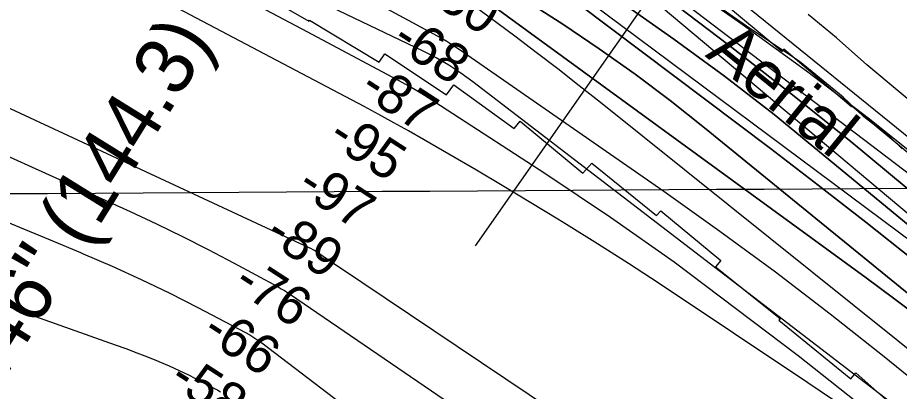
# Model space of a CAD drawing. Extents: x 3477039 to 3515015, y 546746 to 572297.
# Drawn here: x 3498864 to 3500384, y 563990 to 564634 of the extents above; entities that cross this region are included whole.
import ezdxf

# ---------------------------------------------------------------- set-up
doc = ezdxf.new("R2010")
doc.units = 0
for name, color, linetype in [('V-CHAN-NAID', 7, 'Continuous'), ('V-GRID-MAJR', 7, 'Continuous'), ('V-RIVR-EDGE', 7, 'Continuous'), ('V-RIVR-IDEN', 7, 'Continuous'), ('V-RIVR-RANG', 7, 'Continuous'), ('V-RRAP-RVMT', 7, 'Continuous'), ('V-SITE-VEGE', 7, 'Continuous'), ('V-TOPO-DPTH', 7, 'Continuous'), ('V-TOPO-MAJR', 7, 'Continuous'), ('V-TOPO-MINR', 7, 'Continuous'), ('V-TOPO-WATR', 7, 'Continuous')]:
    doc.layers.add(name, color=color, linetype=linetype)

msp = doc.modelspace()

# ---------------------------------------------------------------- linework, layer by layer
at = {"layer": 'V-GRID-MAJR'}
msp.add_spline([(3481202, 564229.3), (3486474.8, 564258.8), (3491747.6, 564289.1), (3497020.4, 564320.1), (3502293.2, 564352), (3507566, 564384.6), (3512838.8, 564417.9)], degree=3, dxfattribs=at)
at = {"layer": 'V-RIVR-EDGE'}
msp.add_lwpolyline([(3500388.8, 564408.2), (3500367.4, 564429), (3500322.7, 564463.5), (3500287.3, 564497.3), (3500212.1, 564558.7), (3500120.3, 564619.6), (3500042, 564675.6)], dxfattribs=at)
at = {"layer": 'V-RIVR-RANG'}
msp.add_line((3500202.8, 565027.4), (3499652.6, 564240.7), dxfattribs=at)
at = {"layer": 'V-RRAP-RVMT'}
for points in [[(3499250, 564694.8), (3499365.7, 564628.1), (3499366.9, 564630.1), (3499487.3, 564557.6), (3499496.8, 564572.2), (3499603.4, 564501.2), (3499615.9, 564518.3), (3499719.6, 564443), (3499730, 564455.9), (3499838.5, 564366.1), (3499853.9, 564383.4), (3499965.5, 564293.5), (3499972.7, 564301.4), (3500076.1, 564215.4), (3500067.3, 564205), (3500178.5, 564115.8), (3500176.4, 564113), (3500300.2, 564011.6), (3500309.2, 564022.1), (3500402.1, 563939.2)], [(3499250, 564694.8), (3499365.7, 564628.1), (3499366.9, 564630.1), (3499487.3, 564557.6), (3499496.8, 564572.2), (3499603.4, 564501.2), (3499615.9, 564518.3), (3499719.6, 564443), (3499730, 564455.9), (3499838.5, 564366.1), (3499853.9, 564383.4), (3499965.5, 564293.5), (3499972.7, 564301.4), (3500076.1, 564215.4), (3500067.3, 564205), (3500178.5, 564115.8), (3500176.4, 564113), (3500300.2, 564011.6), (3500309.2, 564022.1), (3500402.1, 563939.2)], [(3500409.1, 564392.5), (3500302.5, 564481.5), (3500301.8, 564480.6), (3500185, 564580.1), (3500181.4, 564576), (3500072.7, 564666.9)]]:
    msp.add_lwpolyline(points, dxfattribs=at)
at = {"layer": 'V-SITE-VEGE'}
msp.add_lwpolyline([(3500436.3, 564462.7), (3500328.2, 564553.3), (3500275.6, 564599.6), (3500226.9, 564639.9)], dxfattribs=at)
at = {"layer": 'V-TOPO-DPTH'}
for points in [[(3500399.3, 564338.4), (3500297.7, 564423), (3500194.4, 564505.6), (3500090, 564586.8), (3499774, 564827.2), (3499767.9, 564831.6), (3499761.7, 564835.8), (3499755.3, 564839.7), (3499748.8, 564843.4), (3499634.5, 564904.6), (3499306.4, 565053.7), (3499251, 565076.9), (3499195.6, 565100.2), (3499113.9, 565134.7), (3499018.4, 565174.5), (3498922.7, 565213.8), (3498826.7, 565252.4), (3498730.4, 565290.4), (3498562.1, 565356.3), (3498549.9, 565360.9), (3498537.6, 565365.4), (3498525.2, 565369.7), (3498512.8, 565373.8), (3497462.6, 565684.4)], [(3497462.6, 565684.4), (3498512.8, 565373.8), (3498525.2, 565369.7), (3498537.6, 565365.4), (3498549.9, 565360.9), (3498562.1, 565356.3), (3498730.4, 565290.4), (3498826.7, 565252.4), (3498922.7, 565213.8), (3499018.4, 565174.5), (3499113.9, 565134.7), (3499195.6, 565100.2), (3499251, 565076.9), (3499306.4, 565053.7), (3499634.5, 564904.6), (3499748.8, 564843.4), (3499755.3, 564839.7), (3499761.7, 564835.8), (3499767.9, 564831.6), (3499774, 564827.2), (3500090, 564586.8), (3500194.4, 564505.6), (3500297.7, 564423), (3500399.3, 564338.4)], [(3500663, 564060), (3500168.5, 564467.3), (3500082.6, 564533.6), (3499995, 564597.5), (3499906.1, 564659.7), (3499767.6, 564753.7), (3499746.8, 564767.3), (3499725.6, 564780.3), (3499703.9, 564792.4), (3499681.8, 564803.9), (3499469.4, 564909.8), (3499211, 565035.2), (3499080.8, 565095.7), (3498950.1, 565155), (3498530.3, 565342.3), (3498529.6, 565342.6), (3498527.3, 565343.4), (3498503, 565351.3), (3498490.1, 565355.4), (3498477.2, 565359.4), (3498464.2, 565363.2), (3498451.1, 565366.8), (3497409.8, 565651.6)], [(3497409.8, 565651.6), (3498451.1, 565366.8), (3498464.2, 565363.2), (3498477.2, 565359.4), (3498490.1, 565355.4), (3498503, 565351.3), (3498527.3, 565343.4), (3498529.6, 565342.6), (3498530.3, 565342.3), (3498950.1, 565155), (3499080.8, 565095.7), (3499211, 565035.2), (3499469.4, 564909.8), (3499681.8, 564803.9), (3499703.9, 564792.4), (3499725.6, 564780.3), (3499746.8, 564767.3), (3499767.6, 564753.7), (3499906.1, 564659.7), (3499995, 564597.5), (3500082.6, 564533.6), (3500168.5, 564467.3), (3500663, 564060)], [(3500420.7, 564115.4), (3500374, 564150.7), (3500327, 564185.6), (3499674, 564661.6), (3499665.1, 564667.8), (3499656.1, 564673.8), (3499646.8, 564679.4), (3499637.4, 564684.8), (3499477.3, 564771.6), (3499387.3, 564819.6), (3499296.9, 564866.7), (3499205.9, 564912.5), (3499114.4, 564957.4), (3498502.6, 565252.5), (3498498.7, 565254.2), (3498494.8, 565255.9), (3498490.9, 565257.3), (3498486.9, 565258.7), (3497389.5, 565556.4)], [(3497389.5, 565556.4), (3498486.9, 565258.7), (3498490.9, 565257.3), (3498494.8, 565255.9), (3498498.7, 565254.2), (3498502.6, 565252.5), (3499114.4, 564957.4), (3499205.9, 564912.5), (3499296.9, 564866.7), (3499387.3, 564819.6), (3499477.3, 564771.6), (3499637.4, 564684.8), (3499646.8, 564679.4), (3499656.1, 564673.8), (3499665.1, 564667.8), (3499674, 564661.6), (3500327, 564185.6), (3500374, 564150.7), (3500420.7, 564115.4)], [(3500595.9, 563998.6), (3500048.1, 564444.6), (3499988.7, 564491.5), (3499928.3, 564537), (3499866.5, 564580.6), (3499803.7, 564623), (3499726.3, 564673.4), (3499701.4, 564689.1), (3499676.1, 564704.3), (3499650.3, 564718.7), (3499015.5, 565037.8), (3498887.4, 565097.3), (3498758.6, 565155.3), (3498520.9, 565260.2), (3498510.4, 565264.6), (3498499.9, 565268.8), (3498489.2, 565272.6), (3498478.5, 565276.2), (3497648.1, 565517.6)], [(3497648.1, 565517.6), (3498478.5, 565276.2), (3498489.2, 565272.6), (3498499.9, 565268.8), (3498510.4, 565264.6), (3498520.9, 565260.2), (3498758.6, 565155.3), (3498887.4, 565097.3), (3499015.5, 565037.8), (3499650.3, 564718.7), (3499676.1, 564704.3), (3499701.4, 564689.1), (3499726.3, 564673.4), (3499803.7, 564623), (3499866.5, 564580.6), (3499928.3, 564537), (3499988.7, 564491.5), (3500048.1, 564444.6), (3500595.9, 563998.6)], [(3500439.7, 564374), (3500332.5, 564459.1), (3500223.9, 564542.4), (3500113.1, 564622.8), (3500001, 564701.4), (3499806.3, 564834.2), (3499790.3, 564844.7), (3499774.1, 564854.9), (3499757.7, 564864.5), (3498726.4, 565353.5)], [(3498819.6, 565170.7), (3498880.3, 565143), (3499125, 565028.7), (3499192.1, 564997.5), (3499259.2, 564966.5), (3499326.5, 564935.7), (3499437.2, 564885.6), (3499482.8, 564864.6), (3499528.1, 564843.1), (3499573.1, 564820.8), (3499617.9, 564798.1), (3499694.3, 564758.4), (3499700.6, 564755), (3499706.6, 564751.4), (3499712.5, 564747.4), (3499718.3, 564743.3), (3500161.9, 564408.7), (3500244.3, 564345.6), (3500326.2, 564281.9), (3500407.3, 564217.2)], [(3498819.6, 565170.7), (3498880.3, 565143), (3499125, 565028.7), (3499192.1, 564997.5), (3499259.2, 564966.5), (3499326.5, 564935.7), (3499437.2, 564885.6), (3499482.8, 564864.6), (3499528.1, 564843.1), (3499573.1, 564820.8), (3499617.9, 564798.1), (3499694.3, 564758.4), (3499700.6, 564755), (3499706.6, 564751.4), (3499712.5, 564747.4), (3499718.3, 564743.3), (3500161.9, 564408.7), (3500244.3, 564345.6), (3500326.2, 564281.9), (3500407.3, 564217.2)]]:
    msp.add_lwpolyline(points, dxfattribs=at)
at = {"layer": 'V-TOPO-MAJR'}
msp.add_lwpolyline([(3500526.5, 563961.2), (3499868.6, 564488.1), (3499832, 564517.1), (3499795.2, 564545.9), (3499758.1, 564574.3), (3499720.8, 564602.4), (3499647.9, 564656.8), (3499646.9, 564657.5), (3499643.8, 564659.4), (3499625.3, 564669.4), (3499615, 564675), (3499604.6, 564680.4), (3499594.2, 564685.8), (3499583.7, 564691), (3499512.5, 564726), (3499466.4, 564748.7), (3499420.2, 564771.2), (3499374, 564793.7), (3499327.8, 564816.1), (3498816, 565063.4)], dxfattribs=at)
at = {"layer": 'V-TOPO-MINR'}
for points in [[(3500718, 564123.4), (3499789.5, 564829.9), (3499778.8, 564837.7), (3499767.8, 564845.2), (3499756.4, 564852.1), (3499744.9, 564858.6), (3498835, 565279.3), (3498781.1, 565301), (3498727, 565322.1), (3498672.7, 565342.8), (3498596.2, 565371.7), (3498571.6, 565380.7), (3498547, 565389.4), (3497441.9, 565732.9)], [(3500726.4, 564163.4), (3499817.6, 564899.8), (3499814.4, 564902.2), (3499812.7, 564903.3), (3499809.3, 564905.3), (3499805.8, 564907.1), (3499804, 564908), (3498775.9, 565377.8), (3498597.3, 565448.8), (3498585.5, 565453.4), (3498573.6, 565457.7), (3498561.6, 565461.8), (3498549.6, 565465.7), (3498290.4, 565546.2), (3498148.4, 565588.9), (3497719.2, 565706.2)], [(3500663, 564060), (3500168.5, 564467.3), (3500082.6, 564533.6), (3499995, 564597.5), (3499906.1, 564659.7), (3499767.6, 564753.7), (3499746.8, 564767.3), (3499725.6, 564780.3), (3499703.9, 564792.4), (3499681.8, 564803.9), (3499469.4, 564909.8), (3499211, 565035.2), (3499080.8, 565095.7), (3498950.1, 565155), (3498530.3, 565342.3), (3498529.6, 565342.6), (3498527.3, 565343.4), (3498503, 565351.3), (3498490.1, 565355.4), (3498477.2, 565359.4), (3498464.2, 565363.2), (3498451.1, 565366.8), (3497409.8, 565651.6)], [(3500420.7, 564115.4), (3500374, 564150.7), (3500327, 564185.6), (3499674, 564661.6), (3499665.1, 564667.8), (3499656.1, 564673.8), (3499646.8, 564679.4), (3499637.4, 564684.8), (3499477.3, 564771.6), (3499387.3, 564819.6), (3499296.9, 564866.7), (3499205.9, 564912.5), (3499114.4, 564957.4), (3498502.6, 565252.5), (3498498.7, 565254.2), (3498494.8, 565255.9), (3498490.9, 565257.3), (3498486.9, 565258.7), (3497389.5, 565556.4)], [(3500595.9, 563998.6), (3500048.1, 564444.6), (3499988.7, 564491.5), (3499928.3, 564537), (3499866.5, 564580.6), (3499803.7, 564623), (3499726.3, 564673.4), (3499701.4, 564689.1), (3499676.1, 564704.3), (3499650.3, 564718.7), (3499015.5, 565037.8), (3498887.4, 565097.3), (3498758.6, 565155.3), (3498520.9, 565260.2), (3498510.4, 565264.6), (3498499.9, 565268.8), (3498489.2, 565272.6), (3498478.5, 565276.2), (3497648.1, 565517.6)], [(3500458.3, 563902.2), (3499648.6, 564523.7), (3499638.4, 564531.2), (3499628.2, 564538.6), (3499617.7, 564545.6), (3499607.1, 564552.4), (3499596.3, 564558.9), (3499585.3, 564565.1), (3499574.2, 564571), (3499562.9, 564576.7), (3498978.8, 564856.8), (3498888.8, 564899), (3498798.3, 564940.1), (3498707.1, 564979.6), (3498615.5, 565018.1), (3498462.7, 565080.6), (3498447, 565086.7), (3498431.2, 565092.6), (3498415.2, 565097.9), (3498399.1, 565103), (3497397.6, 565366.9)], [(3500439.7, 564374), (3500332.5, 564459.1), (3500223.9, 564542.4), (3500113.1, 564622.8), (3500001, 564701.4), (3499806.3, 564834.2), (3499790.3, 564844.7), (3499774.1, 564854.9), (3499757.7, 564864.5), (3498726.4, 565353.5)], [(3500463.7, 563850.1), (3500209.7, 564051.4), (3499995.8, 564212.9), (3499885.9, 564289.6), (3499774.5, 564364.3), (3499571.5, 564496.3), (3499560.5, 564503.3), (3499549.4, 564510), (3499538.1, 564516.5), (3499526.6, 564522.8), (3499364.3, 564609.6), (3499271.4, 564658.5), (3499178.1, 564706.8), (3499084.3, 564754.1), (3498990.1, 564800.6), (3498438.2, 565069.4), (3498431.4, 565072.5), (3498424.5, 565075.4), (3497290.4, 565311.9)], [(3500407.3, 564217.2), (3500326.2, 564281.9), (3500244.3, 564345.6), (3500161.9, 564408.7), (3499718.3, 564743.3), (3499712.5, 564747.4), (3499706.6, 564751.4), (3499700.6, 564755), (3499694.3, 564758.4), (3499617.9, 564798.1), (3499573.1, 564820.8), (3499528.1, 564843.1), (3499482.8, 564864.6), (3499437.2, 564885.6), (3499326.5, 564935.7), (3499259.2, 564966.5), (3499192.1, 564997.5), (3499125, 565028.7), (3498880.3, 565143), (3498819.6, 565170.7)], [(3500495, 564180.6), (3499736.2, 564746.6), (3499725, 564754.5), (3499713.6, 564762), (3499701.8, 564769), (3499689.8, 564775.6), (3499542.1, 564852.2), (3499455.7, 564896.1), (3499368.8, 564939.1), (3499281.2, 564980.6), (3499193.2, 565021.1), (3498972.6, 565120.4), (3498916, 565146), (3498859.5, 565171.7)], [(3500531.2, 563908.7), (3500357.9, 564049.4), (3500264.8, 564123.2), (3500170.5, 564195.7), (3500074.7, 564265.9), (3499977.7, 564334.7), (3499624.8, 564579.3), (3499614.3, 564586.3), (3499603.5, 564593.2), (3499592.6, 564599.6), (3499581.5, 564605.9), (3499398.2, 564705.4), (3499294.8, 564760.1), (3499190.7, 564813.4), (3499085.5, 564864.5), (3498979.6, 564914.1), (3498504.3, 565130.8)], [(3497267.4, 564985), (3498025.7, 564795.1), (3498256, 564725.9), (3498270.3, 564721.4), (3498284.5, 564716.6), (3498298.6, 564711.5), (3498312.6, 564706.1), (3498466.4, 564644.3), (3498556.8, 564607.2), (3498646.9, 564569.1), (3498736.4, 564529.5), (3498825.5, 564489), (3499366.8, 564237.7), (3499368.7, 564236.7), (3499372.5, 564234.8), (3499374.3, 564233.8), (3499378, 564231.6), (3499381.5, 564229.3), (3499390.3, 564223.3), (3499396.5, 564219.1), (3499402.6, 564214.9), (3499408.8, 564210.7), (3499415, 564206.6), (3499912.1, 563873.1)], [(3500392.5, 563884), (3500351.7, 563915.3), (3500310.5, 563946.1), (3500268.6, 563975.8), (3500226.2, 564004.9), (3499970.2, 564175.9), (3499917.1, 564210.4), (3499863.7, 564244.3), (3499810, 564277.7), (3499795.4, 564286.7), (3499748.7, 564315.2), (3499701.8, 564343.4), (3499654.7, 564371.3), (3499607.4, 564398.9), (3499563.3, 564424.5), (3499537.9, 564439), (3499512.4, 564453.3), (3499486.8, 564467.4), (3499461, 564481.2), (3498925.8, 564763.9), (3498839.3, 564807.5), (3498751.8, 564848.7)], [(3500672, 564067.4), (3499938, 564683.3)], [(3498832.3, 564401.8), (3498911.5, 564366.3), (3498990.6, 564330.5), (3499057.9, 564299.9), (3499103, 564278.9), (3499147.8, 564257.2), (3499192.2, 564234.6), (3499236.2, 564211.4), (3499312.8, 564170), (3499318.3, 564167), (3499323.7, 564163.8), (3499329, 564160.4), (3499334.2, 564157), (3499784.3, 563849.6)], [(3498814.2, 564295.1), (3498866.9, 564273.1), (3498919.6, 564251.1), (3498972.3, 564229.2), (3498976.7, 564227.3), (3499026.9, 564205.7), (3499076.7, 564183.2), (3499125.9, 564159.3), (3499174.6, 564134.6), (3499256.7, 564091.5), (3499264, 564087.4), (3499271.1, 564083.1), (3499278, 564078.5), (3499284.7, 564073.6), (3499601.8, 563831.6)], [(3498793.2, 564156.7), (3498884.8, 564122.5), (3499031.7, 564070.5), (3499050.4, 564063.7), (3499069, 564056.7), (3499087.5, 564049.5), (3499105.9, 564042), (3499107, 564041.6), (3499124.8, 564034), (3499142.4, 564026.1), (3499159.7, 564017.7), (3499176.9, 564009), (3499205.7, 563993.9), (3499208.4, 563992.4), (3499210.9, 563990.8), (3499213.4, 563989.1)]]:
    msp.add_lwpolyline(points, dxfattribs=at)
at = {"layer": 'V-TOPO-WATR'}
msp.add_lwpolyline([(3500399.3, 564338.4), (3500297.7, 564423), (3500194.4, 564505.6), (3500090, 564586.8), (3499774, 564827.2), (3499767.9, 564831.6), (3499761.7, 564835.8), (3499755.3, 564839.7), (3499748.8, 564843.4), (3499634.5, 564904.6), (3499306.4, 565053.7), (3499251, 565076.9), (3499195.6, 565100.2), (3499113.9, 565134.7), (3499018.4, 565174.5), (3498922.7, 565213.8), (3498826.7, 565252.4), (3498730.4, 565290.4), (3498562.1, 565356.3), (3498549.9, 565360.9), (3498537.6, 565365.4), (3498525.2, 565369.7), (3498512.8, 565373.8), (3497462.6, 565684.4)], dxfattribs=at)

# ---------------------------------------------------------------- texts
at = {"layer": 'V-CHAN-NAID'}
msp.add_text('ANGELINA "146" (144.3)', height=100, rotation=58.1906, dxfattribs=at).set_placement((3498416.1, 563325.9))
at = {"layer": 'V-RIVR-IDEN'}
msp.add_text('Aerial', height=83, rotation=320.911, dxfattribs=at).set_placement((3500047.8, 564568.5))
at = {"layer": 'V-RIVR-RANG'}
for s, p in [('-50', (3499558.2, 564672.3)), ('-68', (3499505.6, 564587.2)), ('-87', (3499450.3, 564503.9)), ('-95', (3499395.5, 564420.2)), ('-97', (3499342, 564335.7)), ('-89', (3499287, 564252.2)), ('-76', (3499232.6, 564168.3)), ('-66', (3499178.4, 564084.3)), ('-58', (3499121.6, 564001.9))]:
    msp.add_text(s, height=67, rotation=327.0465, dxfattribs=at).set_placement(p)

doc.saveas('drawing.dxf')
